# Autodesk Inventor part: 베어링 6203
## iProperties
IsCustomPart: 0
Company: 한국ATC센터
Created: 2014-08
Part Number: 베어링 6203
Material: 강, 연강
Description: 깊은 그루브 볼 베어링
Document SubType Name: Modeling
Standard: KS B 2023
Designer: KYOUNG IL JANG
Standards Organization: KS
Language: ko-KR
Size Designation: 6203 - 17 x 40 x 12
Categories: <MemberInstance><Categories><Category DisplayName="샤프트 부품" InternalName="7f7aeb1f-a693-4053-b835-cee3144e0d98" Mnemonic="SHFT"><Category DisplayName="베어링" Inter
Density: 7.86 g/cm^3
Mass: 64.9809 g
Surface Area: 64.3582 cm^2
Volume: 8.26729 cm^3
Author: KYOUNG IL JANG
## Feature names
1. IDS_ARRAYBALL[SIMPL:T] [Circular Pattern]
